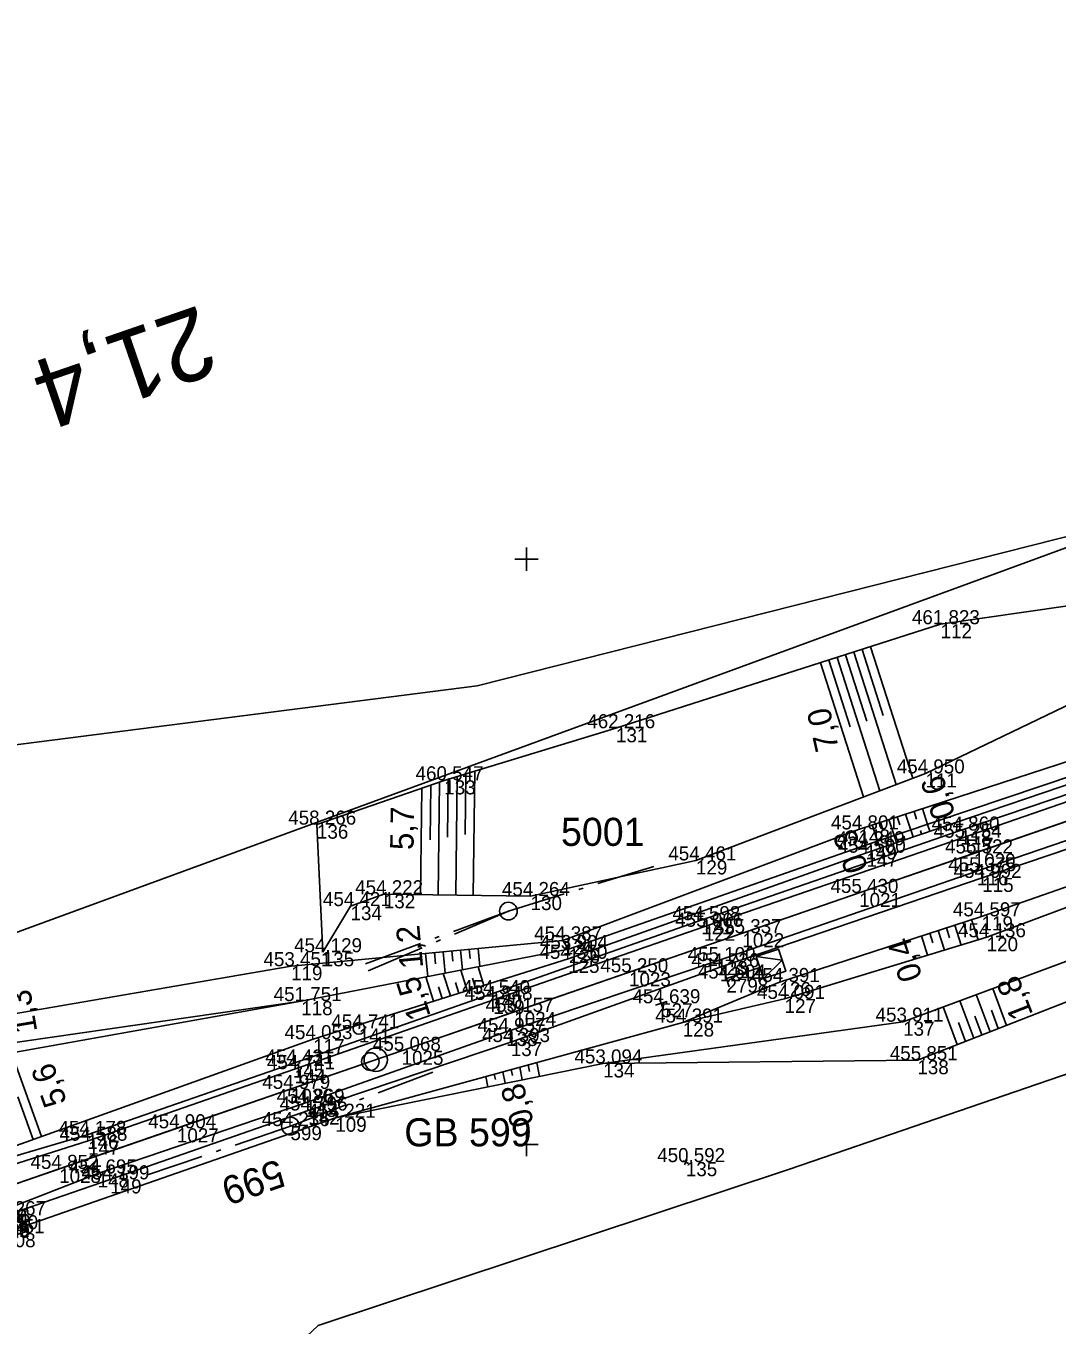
# Model space of a CAD drawing. Extents: x -776734 to -748832, y -1118122 to -976986.
# Drawn here: x -751042.8 to -750954.7, y -1114665.5 to -1114554.4 of the extents above; entities that cross this region are included whole.
import ezdxf

# ---------------------------------------------------------------- set-up
doc = ezdxf.new("R2010")
doc.units = 0
for name, color, linetype in [('KM_Hranice parcel', 7, 'Continuous'), ('Level 61 Křížky', 7, 'Continuous'), ('OSA', 7, 'Continuous'), ('SŽG Vrstva 1', 7, 'Continuous'), ('SŽG Vrstva 4', 7, 'Continuous'), ('SŽG Vrstva 48', 7, 'Continuous'), ('SŽG Vrstva 49', 7, 'Continuous'), ('SŽG Vrstva 53', 7, 'Continuous'), ('SŽG Vrstva 60', 7, 'Continuous'), ('SŽG Vrstva 61', 7, 'Continuous'), ('SŽG Vrstva 63', 7, 'Continuous'), ('SŽG Vrstva 7', 7, 'Continuous'), ('SŽG Vrstva 8', 7, 'Continuous'), ('Vrstva 63 ŽBP', 7, 'Continuous')]:
    doc.layers.add(name, color=color, linetype=linetype)

msp = doc.modelspace()

# ---------------------------------------------------------------- linework, layer by layer
at = {"layer": 'KM_Hranice parcel'}
for points in [[(-751123.4, -1114617.49), (-751113.24, -1114617.58), (-751102.68, -1114616.94), (-751084.8, -1114616.01), (-751048.12, -1114616.42), (-751004.23, -1114610.82), (-750945.62, -1114595.97)], [(-751091.59, -1114651.24), (-751052.09, -1114634.98), (-750945.62, -1114595.97)], [(-750903.28, -1114626.63), (-750977.55, -1114652.09), (-751017.8, -1114665.47), (-751047.63, -1114693.52)]]:
    msp.add_lwpolyline(points, dxfattribs=at)
at = {"layer": 'Level 61 Křížky'}
for p, q in [((-751000, -1114600), (-751000, -1114599)), ((-751001, -1114600), (-750999, -1114600)), ((-751000, -1114601), (-751000, -1114600)), ((-751000, -1114650), (-751000, -1114649)), ((-751000, -1114650), (-751000, -1114649)), ((-751001, -1114650), (-750999, -1114650)), ((-751001, -1114650), (-750999, -1114650)), ((-751000, -1114651), (-751000, -1114650)), ((-751000, -1114651), (-751000, -1114650))]:
    msp.add_line(p, q, dxfattribs=at)
at = {"layer": 'OSA'}
msp.add_line((-751221.2426, -1114714.6428), (-750912.9148, -1114608.268), dxfattribs=at)
msp.add_circle((-751012.8797, -1114642.7554), 1, dxfattribs=at)
at = {"layer": 'SŽG Vrstva 1'}
msp.add_lwpolyline([(-750952.239, -1114621.829), (-750961.799, -1114625.127), (-750971.586, -1114628.505), (-750981.562, -1114631.945), (-750991.246, -1114635.286), (-751001.048, -1114638.665), (-751010.672, -1114641.989), (-751020.123, -1114645.246), (-751029.869, -1114648.612), (-751039.93, -1114652.08), (-751049.798, -1114655.49)], dxfattribs=at)
at = {"layer": 'SŽG Vrstva 4'}
for p, q in [((-751037.448, -1114649.672), (-751047.485, -1114652.852)), ((-751036.639, -1114652.467), (-751046.217, -1114656.195))]:
    msp.add_line(p, q, dxfattribs=at)
for points in [[(-750909.854, -1114605.662), (-750913.632, -1114606.277), (-750928.936, -1114611.392), (-750945.448, -1114617.255), (-750962.947, -1114623.179), (-750985.088, -1114630.83), (-751003.049, -1114637.15), (-751019.956, -1114643.079), (-751037.537, -1114649.178), (-751047.428, -1114652.085)], [(-750909.854, -1114605.662), (-750913.482, -1114606.81), (-750928.752, -1114612.038), (-750945.395, -1114617.786), (-750962.769, -1114623.789), (-750984.849, -1114631.395), (-751002.837, -1114637.648), (-751019.817, -1114643.56), (-751037.448, -1114649.672)], [(-750908.397, -1114608.245), (-750913.156, -1114610.918), (-750927.279, -1114615.559), (-750944.077, -1114621.468), (-750961.07, -1114627.222), (-750983.47, -1114634.851), (-751001.346, -1114641.244), (-751018.647, -1114647.092), (-751035.567, -1114652.973), (-751044.403, -1114656.035)], [(-750908.397, -1114608.245), (-750913.028, -1114609.922), (-750927.564, -1114615.039), (-750944.227, -1114620.718), (-750961.521, -1114626.651), (-750983.784, -1114634.327), (-751001.734, -1114640.382), (-751018.892, -1114646.443), (-751036.639, -1114652.467)]]:
    msp.add_lwpolyline(points, dxfattribs=at)
at = {"layer": 'SŽG Vrstva 48'}
for p, q in [((-750973.4744, -1114608.3847), (-750969.8251, -1114619.7747)), ((-750972.7602, -1114608.1559), (-750970.9415, -1114613.8322)), ((-750972.046, -1114607.927), (-750968.4205, -1114619.2424)), ((-750971.3317, -1114607.6982), (-750969.525, -1114613.3372)), ((-750970.6175, -1114607.4694), (-750967.0159, -1114618.7102)), ((-750974.9029, -1114608.8424), (-750971.2296, -1114620.3069)), ((-750974.1887, -1114608.6136), (-750972.358, -1114614.3272)), ((-751005.1797, -1114618.3253), (-751005.2417, -1114623.5144)), ((-751004.4269, -1114618.0969), (-751004.5539, -1114628.7124)), ((-751008.9446, -1114619.553), (-751009.0535, -1114628.6586)), ((-751008.1914, -1114619.2909), (-751008.2475, -1114623.9792)), ((-751007.4382, -1114619.0287), (-751007.5537, -1114628.6765)), ((-751006.6852, -1114618.7821), (-751006.7445, -1114623.7338)), ((-751005.9325, -1114618.5537), (-751006.0538, -1114628.6944)), ((-750967.616, -1114621.77), (-750967.173, -1114623.131)), ((-750966.902, -1114621.537), (-750966.682, -1114622.215)), ((-750966.189, -1114621.305), (-750965.751, -1114622.653)), ((-750970.468, -1114622.698), (-750970.016, -1114624.089)), ((-750969.755, -1114622.466), (-750969.53, -1114623.158)), ((-750969.042, -1114622.234), (-750968.594, -1114623.61)), ((-750968.329, -1114622.002), (-750968.106, -1114622.686)), ((-750965.546, -1114623.232), (-750965.743, -1114622.65)), ((-750968.387, -1114624.196), (-750968.586, -1114623.607)), ((-750967.676, -1114623.955), (-750967.776, -1114623.661)), ((-750966.966, -1114623.714), (-750967.165, -1114623.129)), ((-750966.256, -1114623.473), (-750966.355, -1114623.181)), ((-750969.807, -1114624.678), (-750970.008, -1114624.086)), ((-750969.097, -1114624.437), (-750969.197, -1114624.142)), ((-750964.8497, -1114631.7146), (-750964.3043, -1114633.3927)), ((-750964.1364, -1114631.4828), (-750963.8616, -1114632.3283)), ((-750963.4231, -1114631.2509), (-750962.8693, -1114632.9548)), ((-750962.7099, -1114631.0191), (-750962.4309, -1114631.8775)), ((-750961.9966, -1114630.7873), (-750961.4344, -1114632.5169)), ((-750966.2762, -1114632.1782), (-750965.7392, -1114633.8306)), ((-750965.5629, -1114631.9464), (-750965.2923, -1114632.779)), ((-751008.624, -1114633.673), (-751008.437, -1114635.643)), ((-751007.877, -1114633.602), (-751007.787, -1114634.55)), ((-751007.13, -1114633.531), (-751006.957, -1114635.354)), ((-751006.384, -1114633.46), (-751006.301, -1114634.335)), ((-751005.637, -1114633.389), (-751005.478, -1114635.066)), ((-751004.89, -1114633.318), (-751004.814, -1114634.12)), ((-751004.144, -1114633.248), (-751003.998, -1114634.778)), ((-751005.076, -1114636.854), (-751005.629, -1114635.096)), ((-751003.645, -1114636.403), (-751004.148, -1114634.807)), ((-751007.937, -1114637.755), (-751008.593, -1114635.673)), ((-751006.506, -1114637.305), (-751007.111, -1114635.384)), ((-751005.791, -1114637.079), (-751006.081, -1114636.16)), ((-751004.36, -1114636.628), (-751004.624, -1114635.79)), ((-751007.222, -1114637.53), (-751007.537, -1114636.529)), ((-750960.406, -1114640.363), (-750961.584, -1114637.188)), ((-750959.009, -1114639.816), (-750960.177, -1114636.667)), ((-750963.201, -1114641.456), (-750964.397, -1114638.231)), ((-750961.804, -1114640.91), (-750962.99, -1114637.71)), ((-750962.502, -1114641.183), (-750963.098, -1114639.577)), ((-750961.105, -1114640.636), (-750961.696, -1114639.043)), ((-750959.708, -1114640.09), (-750960.294, -1114638.509)), ((-751041.444, -1114649.303), (-751043.996, -1114642.17)), ((-751002.7569, -1114643.9888), (-751002.6627, -1114644.4531)), ((-751002.0319, -1114643.7902), (-751001.8335, -1114644.7684)), ((-751001.3069, -1114643.5916), (-751001.2027, -1114644.1054)), ((-751000.5819, -1114643.3929), (-751000.3635, -1114644.4703)), ((-750999.8569, -1114643.1943), (-750999.7427, -1114643.7578)), ((-750999.132, -1114642.9957), (-750998.8934, -1114644.1722)), ((-751003.4819, -1114644.1875), (-751003.3036, -1114645.0665)), ((-751042.15, -1114649.556), (-751043.448, -1114645.93))]:
    msp.add_line(p, q, dxfattribs=at)
at = {"layer": 'SŽG Vrstva 49'}
for p, q in [((-750996.896, -1114632.559), (-750996.404, -1114633.299)), ((-751058.95, -1114643.469), (-751019.246, -1114637.748)), ((-750967.828, -1114639.504), (-750993.458, -1114643.07)), ((-750966.612, -1114642.791), (-750993.458, -1114643.07)), ((-750993.458, -1114643.07), (-751016.335, -1114647.709)), ((-750986.1662, -1114651.6104), (-750986.6158, -1114651.3916)), ((-750986.2816, -1114651.2762), (-750986.5004, -1114651.7258))]:
    msp.add_line(p, q, dxfattribs=at)
for points in [[(-750914.284, -1114599.037), (-750918.732, -1114597.886), (-750932.03, -1114599.468), (-750940.019, -1114601.94), (-750946.634, -1114602.952), (-750964.627, -1114605.55), (-750992.361, -1114614.436), (-751007.031, -1114618.887), (-751017.906, -1114622.672), (-751017.405, -1114633.573)], [(-750914.284, -1114599.037), (-750918.793, -1114599.925), (-750945.255, -1114608.376), (-750965.923, -1114618.296), (-750985.53, -1114625.726), (-750999.654, -1114628.771), (-751012.193, -1114628.621), (-751015.037, -1114629.632), (-751017.405, -1114633.573)], [(-750971.64, -1114623.079), (-750922.658, -1114607.141), (-750911.92, -1114603.429)], [(-750912.493, -1114604.315), (-750923.138, -1114608.3), (-750971.049, -1114624.437)], [(-750911.848, -1114604.924), (-750922.676, -1114608.685), (-750970.963, -1114625.07)], [(-750907.433, -1114611.535), (-750909.429, -1114611.74), (-750926.275, -1114617.369), (-750943.057, -1114624.185), (-750961.128, -1114630.505), (-750978.395, -1114636.117), (-750986.658, -1114639.578), (-751016.335, -1114647.709)], [(-750986.658, -1114639.578), (-750977.954, -1114637.558), (-750960.694, -1114632.291), (-750942.145, -1114625.351), (-750926.015, -1114618.435), (-750909.195, -1114613.036), (-750906.794, -1114617.513)], [(-750906.794, -1114617.513), (-750919.397, -1114621.544), (-750967.828, -1114639.504)], [(-750904.524, -1114618.563), (-750918.921, -1114624.132), (-750966.612, -1114642.791)], [(-750971.64, -1114623.079), (-750996.896, -1114632.559), (-751020.117, -1114634.765)], [(-750970.963, -1114625.07), (-750996.446, -1114634.135), (-751018.226, -1114640.997), (-751047.344, -1114651.414), (-751047.645, -1114652.397)], [(-750971.049, -1114624.437), (-750996.404, -1114633.299), (-751019.246, -1114637.748)], [(-751020.117, -1114634.765), (-751060.04, -1114641.62), (-751070.127, -1114648.352), (-751076.528, -1114658.314), (-751078.11, -1114663.715)], [(-751019.246, -1114637.748), (-751058.49, -1114644.759), (-751068.921, -1114649.956), (-751075.459, -1114658.878), (-751078.11, -1114663.715)], [(-751016.335, -1114647.709), (-751044.621, -1114657.572), (-751046.052, -1114656.653)]]:
    msp.add_lwpolyline(points, dxfattribs=at)
at = {"layer": 'SŽG Vrstva 53'}
for points in [[(-751091.59, -1114651.24), (-751052.09, -1114634.98), (-750945.62, -1114595.97), (-750923.65, -1114590.78), (-750909.46, -1114590.94), (-750904.52, -1114591.74), (-750900.07, -1114579.45), (-750884.93, -1114572.87), (-750860.41, -1114581.47), (-750789.41, -1114554.45)], [(-750804.97, -1114584.92), (-750894.76, -1114611.21), (-750899.97, -1114614.15), (-750906.35, -1114617.75), (-750903.28, -1114626.63), (-750977.55, -1114652.09), (-751017.8, -1114665.47), (-751047.63, -1114693.52)]]:
    msp.add_lwpolyline(points, dxfattribs=at)
at = {"layer": 'SŽG Vrstva 60'}
for p, q in [((-750964.627, -1114605.55), (-750964.627, -1114605.55)), ((-750992.361, -1114614.436), (-750992.361, -1114614.436)), ((-750965.923, -1114618.296), (-750965.923, -1114618.296)), ((-751007.031, -1114618.887), (-751007.031, -1114618.887)), ((-751017.906, -1114622.672), (-751017.906, -1114622.672)), ((-750971.64, -1114623.079), (-750971.64, -1114623.079)), ((-750962.947, -1114623.179), (-750962.947, -1114623.179)), ((-750962.769, -1114623.789), (-750962.769, -1114623.789)), ((-750971.049, -1114624.437), (-750971.049, -1114624.437)), ((-750970.963, -1114625.07), (-750970.963, -1114625.07)), ((-750961.799, -1114625.127), (-750961.799, -1114625.127)), ((-750985.53, -1114625.726), (-750985.53, -1114625.726)), ((-750961.521, -1114626.651), (-750961.521, -1114626.651)), ((-750961.07, -1114627.222), (-750961.07, -1114627.222)), ((-751012.193, -1114628.621), (-751012.193, -1114628.621)), ((-750999.654, -1114628.771), (-750999.654, -1114628.771)), ((-750971.586, -1114628.505), (-750971.586, -1114628.505)), ((-751015.037, -1114629.632), (-751015.037, -1114629.632)), ((-750961.128, -1114630.505), (-750961.128, -1114630.505)), ((-750985.088, -1114630.83), (-750985.088, -1114630.83)), ((-750984.849, -1114631.395), (-750984.849, -1114631.395)), ((-750996.896, -1114632.559), (-750996.896, -1114632.559)), ((-750981.562, -1114631.945), (-750981.562, -1114631.945)), ((-750960.694, -1114632.291), (-750960.694, -1114632.291)), ((-751017.405, -1114633.573), (-751017.405, -1114633.573)), ((-750996.404, -1114633.299), (-750996.404, -1114633.299)), ((-751020.117, -1114634.765), (-751020.117, -1114634.765)), ((-750996.446, -1114634.135), (-750996.446, -1114634.135)), ((-750983.784, -1114634.327), (-750983.784, -1114634.327)), ((-750983.47, -1114634.851), (-750983.47, -1114634.851)), ((-750991.246, -1114635.286), (-750991.246, -1114635.286)), ((-750982.921, -1114635.817), (-750982.921, -1114635.817)), ((-750978.395, -1114636.117), (-750978.395, -1114636.117)), ((-751003.049, -1114637.15), (-751003.049, -1114637.15)), ((-751019.246, -1114637.748), (-751019.246, -1114637.748)), ((-751002.837, -1114637.648), (-751002.837, -1114637.648)), ((-750988.5, -1114637.931), (-750988.5, -1114637.931)), ((-750977.954, -1114637.558), (-750977.954, -1114637.558)), ((-751001.048, -1114638.665), (-751001.048, -1114638.665)), ((-750967.828, -1114639.504), (-750967.828, -1114639.504)), ((-751014.322, -1114640.079), (-751014.322, -1114640.079)), ((-751001.734, -1114640.382), (-751001.734, -1114640.382)), ((-750986.658, -1114639.578), (-750986.658, -1114639.578)), ((-751018.226, -1114640.997), (-751018.226, -1114640.997)), ((-751001.346, -1114641.244), (-751001.346, -1114641.244)), ((-751010.672, -1114641.989), (-751010.672, -1114641.989)), ((-750966.612, -1114642.791), (-750966.612, -1114642.791)), ((-751019.956, -1114643.079), (-751019.956, -1114643.079)), ((-751019.817, -1114643.56), (-751019.817, -1114643.56)), ((-750993.458, -1114643.07), (-750993.458, -1114643.07)), ((-751020.123, -1114645.246), (-751020.123, -1114645.246)), ((-751018.892, -1114646.443), (-751018.892, -1114646.443)), ((-751018.647, -1114647.092), (-751018.647, -1114647.092)), ((-751020.168, -1114648.425), (-751020.168, -1114648.425)), ((-751016.335, -1114647.709), (-751016.335, -1114647.709)), ((-751037.537, -1114649.178), (-751037.537, -1114649.178)), ((-751029.869, -1114648.612), (-751029.869, -1114648.612)), ((-751037.448, -1114649.672), (-751037.448, -1114649.672)), ((-750986.391, -1114651.501), (-750986.391, -1114651.501)), ((-751039.93, -1114652.08), (-751039.93, -1114652.08)), ((-751036.639, -1114652.467), (-751036.639, -1114652.467)), ((-751035.567, -1114652.973), (-751035.567, -1114652.973))]:
    msp.add_line(p, q, dxfattribs=at)
at = {"layer": 'SŽG Vrstva 63'}
msp.add_line((-751020.1207, -1114648.4087), (-751020.2153, -1114648.4413), dxfattribs=at)
msp.add_circle((-751020.168, -1114648.425), 0.756, dxfattribs=at)
at = {"layer": 'SŽG Vrstva 7'}
for p, q in [((-750988.0273, -1114637.7679), (-750988.9727, -1114638.0941)), ((-750988.3369, -1114638.4037), (-750988.6631, -1114637.4583)), ((-751014.2747, -1114640.0627), (-751014.3693, -1114640.0953))]:
    msp.add_line(p, q, dxfattribs=at)
for centre, radius in [((-751014.322, -1114640.079), 0.5), ((-751013.3487, -1114642.9115), 0.75)]:
    msp.add_circle(centre, radius, dxfattribs=at)
at = {"layer": 'SŽG Vrstva 8'}
msp.add_line((-750983.1563, -1114635.1049), (-750982.6857, -1114636.5291), dxfattribs=at)
for points in [[(-750982.921, -1114635.817), (-750980.0725, -1114634.8757), (-750979.7587, -1114635.8252), (-750977.8597, -1114635.1977), (-750978.4872, -1114633.2987), (-750980.3862, -1114633.9262), (-750980.0725, -1114634.8757)], [(-750980.3862, -1114633.9262), (-750978.1735, -1114634.2482), (-750979.7587, -1114635.8252)]]:
    msp.add_lwpolyline(points, dxfattribs=at)
at = {"layer": 'Vrstva 63 ŽBP'}
for p, q in [((-750993.9093, -1114627.7093), (-750989.1298, -1114626.2409)), ((-750995.5343, -1114628.2085), (-750995.1519, -1114628.0911)), ((-751001.5565, -1114630.0587), (-750996.777, -1114628.5903)), ((-751001.5565, -1114630.0587), (-751006.2472, -1114631.7901)), ((-751001.5565, -1114630.0587), (-751006.1572, -1114632.0166)), ((-751001.5971, -1114630.0295), (-751001.5159, -1114630.088)), ((-751009.0616, -1114632.8289), (-751013.7522, -1114634.5603)), ((-751007.4667, -1114632.2403), (-751007.842, -1114632.3788)), ((-751007.3534, -1114632.5256), (-751007.7215, -1114632.6823)), ((-751008.9177, -1114633.1913), (-751013.5184, -1114635.1492)), ((-751012.691, -1114645.58), (-751008.0179, -1114643.8018)), ((-751014.2799, -1114646.1846), (-751013.906, -1114646.0423)), ((-751020.168, -1114648.4252), (-751015.4949, -1114646.6469)), ((-751020.168, -1114648.4249), (-751024.8997, -1114650.0409)), ((-751020.1786, -1114648.3761), (-751020.1574, -1114648.4739)), ((-751026.1299, -1114650.4611), (-751026.5084, -1114650.5904)), ((-751027.7386, -1114651.0106), (-751032.4703, -1114652.6266))]:
    msp.add_line(p, q, dxfattribs=at)
for centre in [(-751001.5565, -1114630.0587), (-751020.168, -1114648.425)]:
    msp.add_circle(centre, 0.756, dxfattribs=at)

# ---------------------------------------------------------------- texts
at = {"layer": 'OSA'}
msp.add_text('21,4', height=6, rotation=199.034988, dxfattribs=at).set_placement((-751027.9388, -1114578.2575))
at = {"layer": 'SŽG Vrstva 48'}
for s, rotation, p in [('7,0', 102.765508, (-750973.3126, -1114616.1694)), ('0,6', 108.024102, (-750963.336, -1114621.828)), ('5,7', 89.190246, (-751009.6599, -1114624.8554)), ('0,3', 108.743374, (-750970.792, -1114626.411)), ('1,2', 95.426825, (-751008.821, -1114634.885)), ('0,4', 108.004837, (-750966.16, -1114635.7005)), ('1,5', 107.487538, (-751008.166, -1114639.012)), ('1,8', 111.367814, (-750956.699, -1114638.87)), ('1,3', 99.742994, (-751041.789, -1114640.312)), ('5,6', 109.684732, (-751039.239, -1114646.369)), ('0,8', 105.322076, (-750999.3408, -1114648.1994))]:
    msp.add_text(s, height=2, rotation=rotation, dxfattribs=at).set_placement(p)
at = {"layer": 'SŽG Vrstva 60'}
for s, p in [('112', (-750964.627, -1114606.75)), ('131', (-750992.361, -1114615.636)), ('111', (-750965.923, -1114619.496)), ('133', (-751007.031, -1114620.087)), ('136', (-751017.906, -1114623.872)), ('148', (-750971.64, -1114624.279)), ('118', (-750962.947, -1114624.379)), ('117', (-750962.769, -1114624.989)), ('149', (-750971.049, -1114625.637)), ('147', (-750970.963, -1114626.27)), ('1020', (-750961.799, -1114626.327)), ('129', (-750985.53, -1114626.926)), ('116', (-750961.521, -1114627.851)), ('115', (-750961.07, -1114628.422)), ('132', (-751012.193, -1114629.821)), ('130', (-750999.654, -1114629.971)), ('1021', (-750971.586, -1114629.705)), ('134', (-751015.037, -1114630.832)), ('119', (-750961.128, -1114631.705)), ('121', (-750985.088, -1114632.03)), ('122', (-750984.849, -1114632.595)), ('124', (-750996.896, -1114633.759)), ('1022', (-750981.562, -1114633.145)), ('120', (-750960.694, -1114633.491)), ('135', (-751017.405, -1114634.773)), ('126', (-750996.404, -1114634.499)), ('119', (-751020.117, -1114635.965)), ('125', (-750996.446, -1114635.335)), ('123', (-750983.784, -1114635.527)), ('124', (-750983.47, -1114636.051)), ('1023', (-750991.246, -1114636.486)), ('2798', (-750982.921, -1114637.017)), ('126', (-750978.395, -1114637.317)), ('140', (-751003.049, -1114638.35)), ('118', (-751019.246, -1114638.948)), ('139', (-751002.837, -1114638.848)), ('527', (-750988.5, -1114639.131)), ('127', (-750977.954, -1114638.758)), ('1024', (-751001.048, -1114639.865)), ('128', (-750986.658, -1114640.778)), ('137', (-750967.828, -1114640.704)), ('141', (-751014.322, -1114641.279)), ('138', (-751001.734, -1114641.582)), ('117', (-751018.226, -1114642.197)), ('137', (-751001.346, -1114642.444)), ('1025', (-751010.672, -1114643.189)), ('138', (-750966.612, -1114643.991)), ('145', (-751019.956, -1114644.279)), ('144', (-751019.817, -1114644.76)), ('134', (-750993.458, -1114644.27)), ('1026', (-751020.123, -1114646.446)), ('143', (-751018.892, -1114647.643)), ('142', (-751018.647, -1114648.292)), ('599', (-751020.168, -1114649.625)), ('109', (-751016.335, -1114648.909)), ('146', (-751037.537, -1114650.378)), ('1027', (-751029.869, -1114649.812)), ('147', (-751037.448, -1114650.872)), ('135', (-750986.391, -1114652.701)), ('1028', (-751039.93, -1114653.28)), ('148', (-751036.639, -1114653.667)), ('149', (-751035.567, -1114654.173)), ('2831', (-751046.217, -1114657.395)), ('150', (-751044.403, -1114657.235)), ('2828', (-751046.052, -1114657.853)), ('2829', (-751046.019, -1114657.961)), ('2830', (-751046.015, -1114657.961)), ('2832', (-751046.01, -1114657.891)), ('108', (-751044.621, -1114658.772))]:
    msp.add_text(s, height=1.2, dxfattribs=at).set_placement(p)
at = {"layer": 'SŽG Vrstva 61'}
for s, p in [('461.823', (-750967.0789, -1114605.55)), ('462.216', (-750994.8129, -1114614.436)), ('454.950', (-750968.374, -1114618.296)), ('460.547', (-751009.4829, -1114618.887)), ('458.266', (-751020.3579, -1114622.672)), ('454.801', (-750973.9974, -1114623.079)), ('454.860', (-750965.398, -1114623.179)), ('455.254', (-750965.22, -1114623.789)), ('454.249', (-750973.5027, -1114624.437)), ('454.500', (-750973.414, -1114625.07)), ('455.522', (-750964.2472, -1114625.127)), ('454.461', (-750987.8874, -1114625.726)), ('455.375', (-750963.9771, -1114626.651)), ('454.992', (-750963.5182, -1114627.222)), ('455.430', (-750974.037, -1114628.505)), ('454.421', (-751017.3944, -1114629.632)), ('454.222', (-751014.6412, -1114628.621)), ('454.264', (-751002.105, -1114628.771)), ('454.597', (-750963.5799, -1114630.505)), ('454.598', (-750987.5417, -1114630.83)), ('455.066', (-750987.3009, -1114631.395)), ('454.387', (-750999.3479, -1114632.559)), ('455.337', (-750984.0139, -1114631.945)), ('454.136', (-750963.1459, -1114632.291)), ('454.129', (-751019.8587, -1114633.573)), ('453.904', (-750998.855, -1114633.299)), ('453.451', (-751022.4744, -1114634.765)), ('454.350', (-750998.897, -1114634.135)), ('455.100', (-750986.235, -1114634.327)), ('454.726', (-750985.9219, -1114634.851)), ('455.250', (-750993.697, -1114635.286)), ('454.604', (-750985.372, -1114635.817)), ('454.391', (-750980.7524, -1114636.117)), ('454.540', (-751005.5, -1114637.15)), ('451.751', (-751021.6034, -1114637.748)), ('454.848', (-751005.2907, -1114637.648)), ('454.639', (-750990.9537, -1114637.931)), ('454.091', (-750980.3114, -1114637.558)), ('455.157', (-751003.4999, -1114638.665)), ('454.391', (-750989.0154, -1114639.578)), ('453.911', (-750970.1854, -1114639.504)), ('454.741', (-751016.6794, -1114640.079)), ('454.957', (-751004.1859, -1114640.382)), ('454.053', (-751020.6779, -1114640.997)), ('454.393', (-751003.7979, -1114641.244)), ('455.068', (-751013.1257, -1114641.989)), ('455.851', (-750968.9694, -1114642.791)), ('454.431', (-751022.3134, -1114643.079)), ('454.741', (-751022.1744, -1114643.56)), ('453.094', (-750995.909, -1114643.07)), ('454.979', (-751022.5767, -1114645.246)), ('454.869', (-751021.3457, -1114646.443)), ('454.396', (-751021.0989, -1114647.092)), ('454.236', (-751022.6199, -1114648.425)), ('454.221', (-751018.6924, -1114647.709)), ('454.178', (-751039.9907, -1114649.178)), ('454.588', (-751039.9017, -1114649.672)), ('454.904', (-751032.32, -1114648.612)), ('450.592', (-750988.8392, -1114651.501)), ('454.852', (-751042.3782, -1114652.08)), ('454.695', (-751039.0951, -1114652.467)), ('454.199', (-751038.0207, -1114652.973)), ('454.267', (-751046.8549, -1114656.035)), ('454.240', (-751048.47, -1114656.761)), ('454.540', (-751048.466, -1114656.761)), ('455.722', (-751048.4582, -1114656.691)), ('454.136', (-751048.2109, -1114656.694)), ('453.751', (-751046.9784, -1114657.572))]:
    msp.add_text(s, height=1.2, dxfattribs=at).set_placement(p)
at = {"layer": 'SŽG Vrstva 63'}
msp.add_text('599', height=2.4, rotation=199.060063, dxfattribs=at).set_placement((-751021.2053, -1114651.2138))
at = {"layer": 'Vrstva 63 ŽBP'}
for s, p in [('5001', (-750997.0601, -1114624.4867)), ('GB 599', (-751010.4491, -1114650.152))]:
    msp.add_text(s, height=2.4, dxfattribs=at).set_placement(p)

doc.saveas('drawing.dxf')
